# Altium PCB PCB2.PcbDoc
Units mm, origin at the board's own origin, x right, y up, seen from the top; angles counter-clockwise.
Board outline 80 x 60 mm, 2 copper layers (Top Layer, Bottom Layer); 29 components, 19 nets, 66 pads, 0 vias.
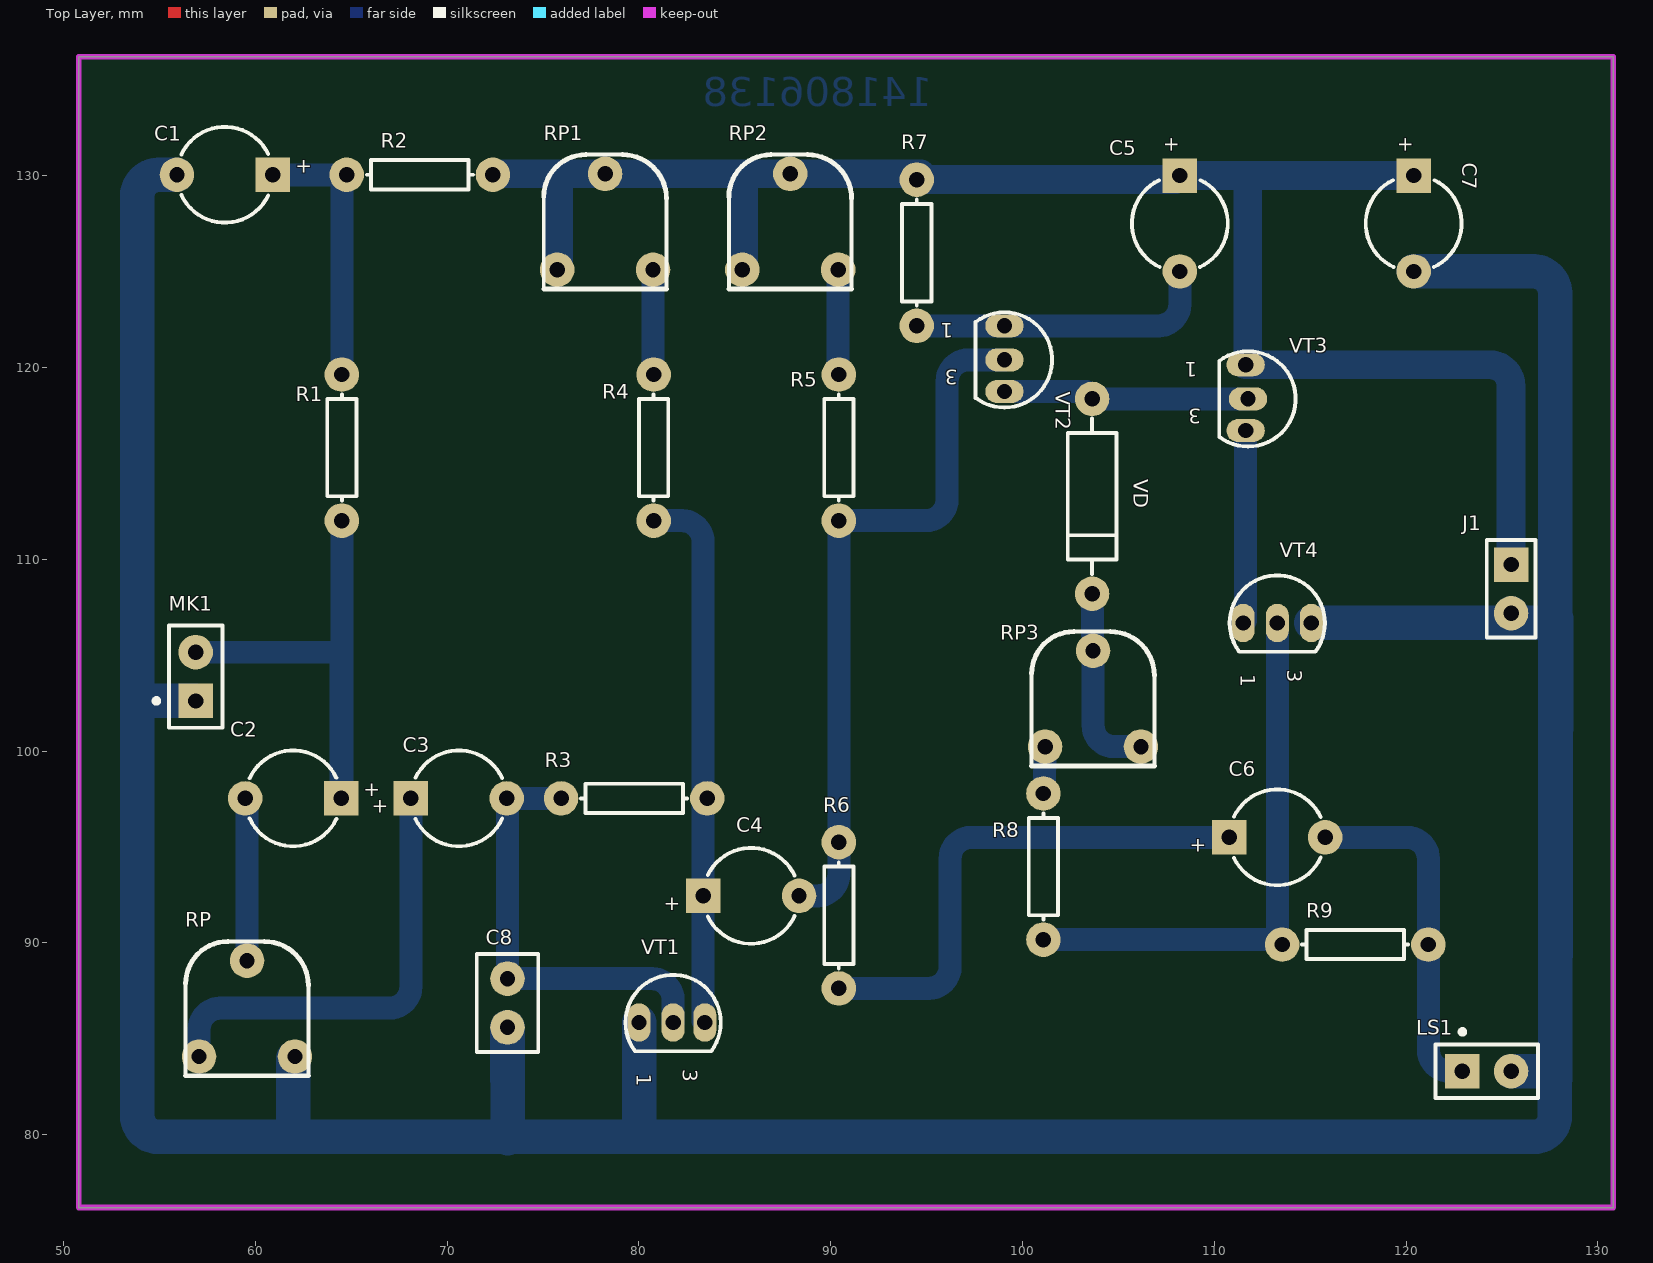
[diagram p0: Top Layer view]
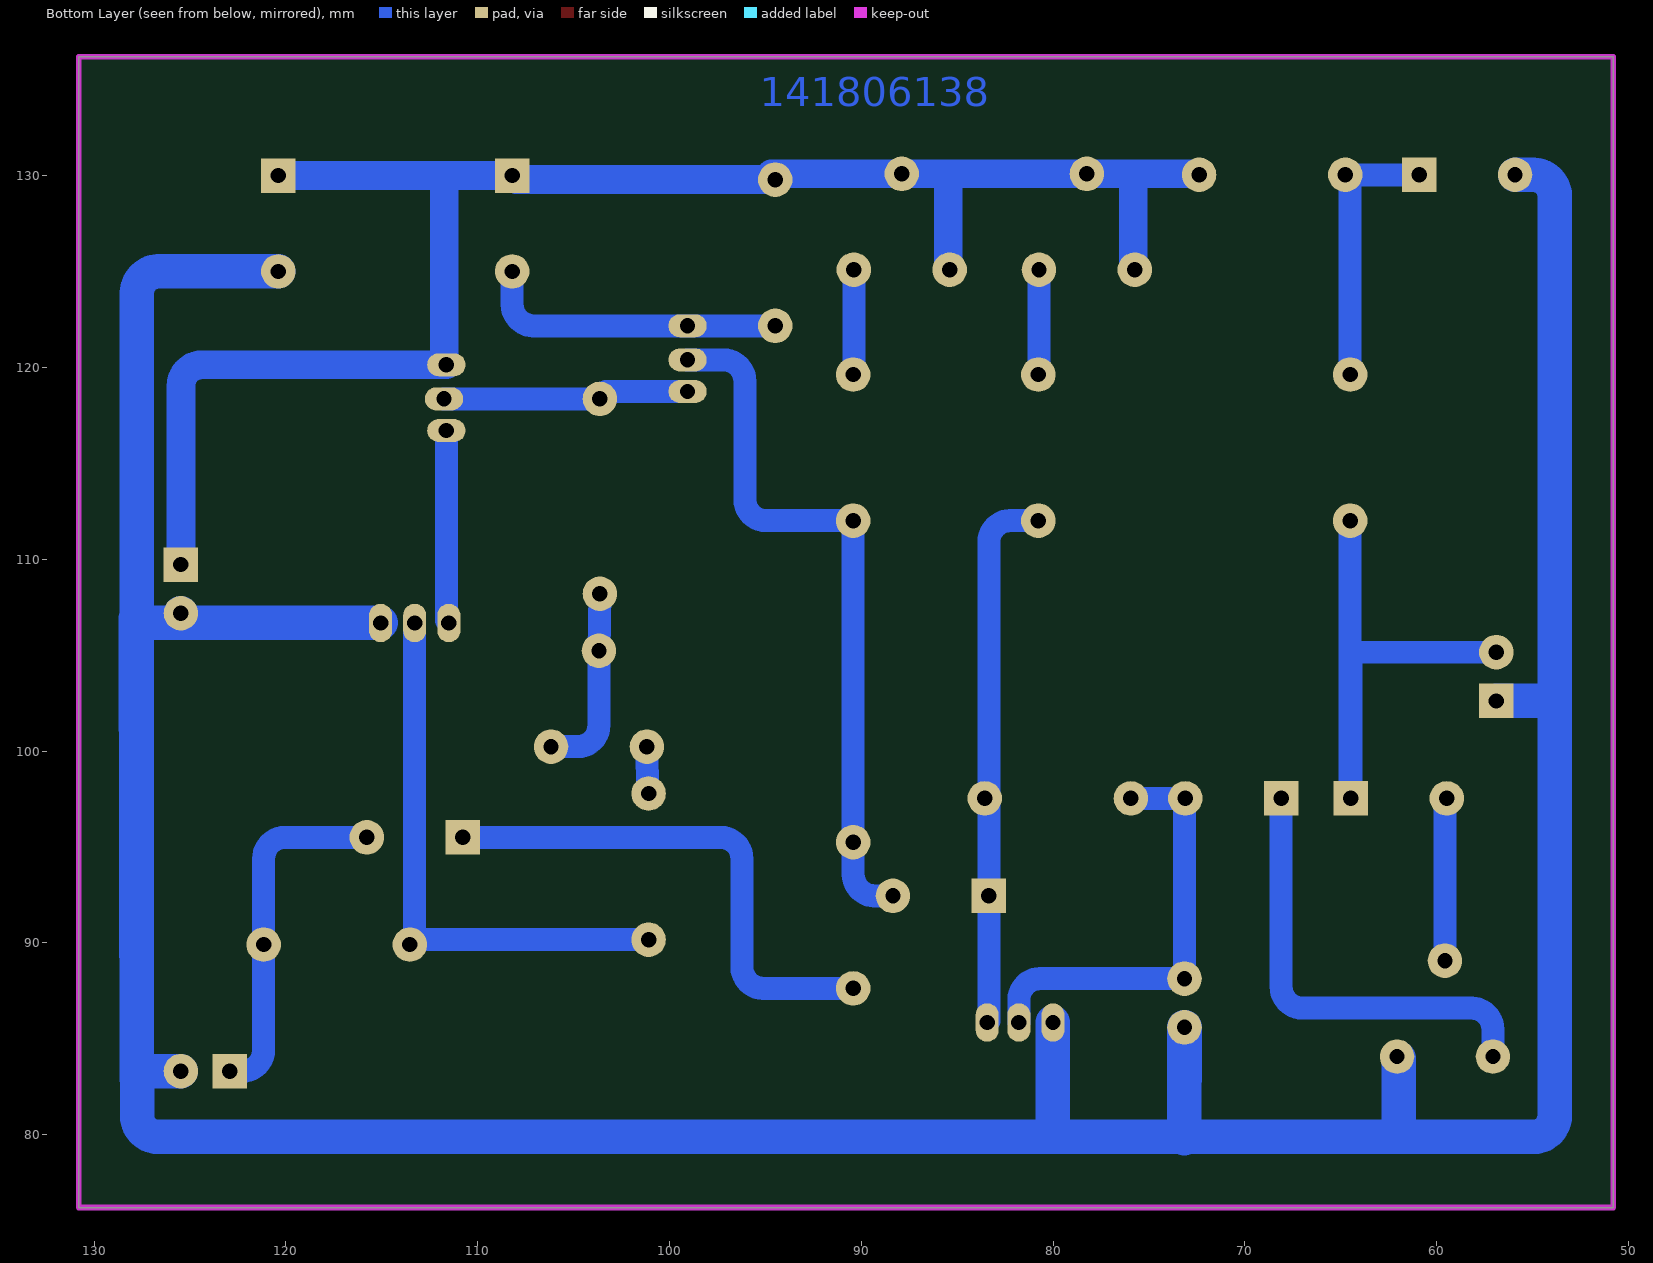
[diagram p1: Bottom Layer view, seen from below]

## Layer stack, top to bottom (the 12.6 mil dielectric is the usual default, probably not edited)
Top Layer: signal copper 0.0356
Dielectric: dielectric 0.32, FR-4, Dk 4.8
Bottom Layer: signal copper 0.0356

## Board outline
50.8,76.2 130.8,76.2 130.8,136.2 50.8,136.2

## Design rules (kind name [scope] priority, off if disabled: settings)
Clearance [All] p1: gap=0.203
ComponentClearance [All] p1: gap=0.254 collisioncheckmode=0
PolygonConnect [All] p1: connectstyle=Relief reliefconductorwidth=0.254 reliefentries=4 polygonreliefangle="90 Angle"
RoutingLayers [All] p1: top layer_v5=FALSE bottom layer_v5=TRUE
RoutingVias [All] p1: holewidth=0.8 width=2 viastyle="Through Hole" minholewidth=0.8 minwidth=1.8 maxholewidth=0.8 maxwidth=2
SolderMaskExpansion [All] p1: expansion=0.102
TestPointUsage [All] p1: valid=0 allowmultiple=FALSE
Testpoint [All] p1: side=15 testpointundercomponent=TRUE minsize=1.016 maxsize=2.54 preferedsize=1.524 minholesize=0 maxholesize=1.016 preferedholesize=0.813 testpointgrid=0.025 style=1023 order=-539222988
Width Width_GND [InNet('GND')] p1: maxlimit=1.8 minlimit=1 preferedwidth=1.8 minimp=50.000000 maximp=50.000000 favimp=50.000000
Width Width_VCC [InNet('VCC')] p2: maxlimit=1.5 minlimit=1.5 preferedwidth=1.5
Width [All] p3: maxlimit=1.2 minlimit=1.2 preferedwidth=1.2
16 further rules are at their usual default settings.

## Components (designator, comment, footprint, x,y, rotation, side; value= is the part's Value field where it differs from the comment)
C1 "Cap Pol1" CAPPR5-5x5 58.42,130.048 r180 top
C2 "Cap Pol1" CAPPR5-5x5 61.976,97.536 r180 top
C3 "Cap Pol1" CAPPR5-5x5 70.612,97.536 r0 top
C4 "Cap Pol1" CAPPR5-5x5 85.852,92.456 r0 top
C5 "Cap Pol1" CAPPR5-5x5 108.204,127.508 r270 top
C6 "Cap Pol1" CAPPR5-5x5 113.284,95.504 r0 top
C7 "Cap Pol1" CAPPR5-5x5 120.396,127.508 r270 top
C8 "Cap" CAPR2.54-5.1x3.2 73.152,86.868 r90 top
J1 "MHDR1X2" HDR1X2 125.476,109.728 r270 top
LS1 "Speaker" PIN2 122.936,83.312 r0 top
MK1 "Mic" PIN2 56.896,102.616 r90 top
R1 "Res2" AXIAL-0.3 64.516,115.824 r90 top
R2 "Res2" AXIAL-0.3 68.58,130.048 r0 top
R3 "Res2" AXIAL-0.3 79.756,97.536 r0 top
R4 "Res2" AXIAL-0.3 80.772,115.824 r90 top
R5 "Res2" AXIAL-0.3 90.424,115.824 r90 top
R6 "Res2" AXIAL-0.3 90.424,91.44 r90 top
R7 "Res2" AXIAL-0.3 94.488,125.984 r90 top
R8 "Res2" AXIAL-0.3 101.092,93.98 r270 top
R9 "Res2" AXIAL-0.3 117.348,89.916 r0 top
RP "RPot" RM065 639.572,989.076 r0 top
RP1 "RPot" RM065 658.241,1030.097 r0 top
RP2 "RPot" RM065 667.893,1030.097 r0 top
RP3 "RPot" RM065 683.679,1005.231 r0 top
VD "4148" DIODE-0.4 103.632,113.284 r270 top
VT1 "9014" BCY-W3/E4#1 81.788,85.852 r270 top
VT2 "9015" BCY-W3/E4#1 99.06,120.396 r180 top
VT3 "8050" BCY-W3/E4#2 111.76,118.364 r180 top
VT4 "8550" BCY-W3/E4#3 113.284,106.68 r270 top

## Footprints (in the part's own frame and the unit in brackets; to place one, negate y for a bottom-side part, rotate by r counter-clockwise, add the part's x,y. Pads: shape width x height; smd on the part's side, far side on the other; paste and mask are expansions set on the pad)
AXIAL-0.3 [mm] "Resistor; 2 Leads"
  round 1.8 hole 0.8: 1(-3.81,0) 2(3.81,0)
  silkscreen extent -2.77,-0.76 2.77,0.76
BCY-W3/E4#1 [mm] "TO, Flat Index; 3 In-Line, Axial Leads; Body Dia. 4.7mm"
  oval 2x1.2 hole 0.8: 1(0,-1.778) 2(0,0) 3(0,1.651)
  silkscreen extent -2.48,-2.48 1.5,2.48
BCY-W3/E4#2 [mm] "TO, Flat Index; 3 In-Line, Axial Leads; Body Dia. 4.7mm"
  oval 2x1.2 hole 0.8: 1(0.127,-1.778) 2(0,0) 3(0.127,1.651)
  silkscreen extent -2.48,-2.48 1.5,2.48
BCY-W3/E4#3 [mm] "TO, Flat Index; 3 In-Line, Axial Leads; Body Dia. 4.7mm"
  oval 2x1.2 hole 0.8: 1(0,-1.778) 2(0,0) 3(0,1.778)
  silkscreen extent -2.48,-2.48 1.5,2.48
CAPPR5-5x5 [mm] "Capacitor, Electrolytic, Radial; Body 5 x 5 mm (Dia.xH typ); Pin Spacing 5 mm (typ)"
  rect 1.8x1.8 hole 0.8: 1(-2.5,0)
  round 1.8 hole 0.8: 2(2.5,0)
  silkscreen extent -2.26,-2.5 2.27,2.5
CAPR2.54-5.1x3.2 [mm] "Capacitor, Ceramic, Thru-Hole, Dipped Radial; Body 5.1 x 3.2 mm (WxT) Pin Spacing 2.54 mm (typ)"
  round 1.8 hole 0.8: 1(-1.27,0) 2(1.27,0)
  silkscreen extent -2.55,-1.6 2.55,1.6
DIODE-0.4 [mm] "Tunnel Diode - Dependent Source Model; 2 Leads"
  round 1.8 hole 0.8: 1(-5.08,0) 2(5.08,0)
  silkscreen extent -4.06,-1.27 4.06,1.27
HDR1X2 [mm] "Connector; Header; 2 Position"
  rect 1.8x1.8 hole 0.8: 1(0,0)
  round 1.8 hole 0.8: 2(2.54,0)
  silkscreen extent -1.27,-1.27 3.81,1.27
PIN2 [mm] "Photosensitive Diode; 2 Leads"
  rect 1.8x1.8 hole 0.8: 1(0,0)
  round 1.8 hole 0.8: 2(2.54,0)
  silkscreen extent -1.4,-1.4 3.94,2.17
RM065 [mm]
  round 1.8 hole 0.8: 1(-582.5,-905) 2(-580,-900) 3(-577.5,-905)
  silkscreen extent -583.2,-906 -576.8,-899

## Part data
C1 C2 C3 C4 C5 C6 C7: "Polarized Capacitor (Radial)"
C8: "Capacitor"
J1: library part "Header 2", "Header, 2-Pin"
LS1: "Loudspeaker"
MK1: library part Mic2, "Microphone"
R1 R2 R3 R4 R5 R6 R7 R8 R9: "Resistor"
RP RP1 RP2 RP3: "Potentiometer"
VD: library part "Diode 1N4148", "High Conductance Fast Diode"
VT1: library part 2N3904, "NPN General Purpose Amplifier"
VT2 VT3 VT4: library part 2N3906, "PNP General Purpose Amplifier"

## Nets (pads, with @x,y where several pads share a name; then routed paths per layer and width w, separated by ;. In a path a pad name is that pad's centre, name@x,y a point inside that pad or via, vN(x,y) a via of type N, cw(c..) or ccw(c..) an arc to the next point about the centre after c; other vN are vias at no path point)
GND: C1.2 C7.2 C8.1 J1.2 LS1.2 MK1.1 RP.3 VT1.1 VT4.3 | length 234.4
  Bottom Layer w1.8: 53.975,102.616 MK1.1 ; C1.2 54.966,130.048 ccw(c54.966,128.93) 53.848,128.93 53.848,81.001 ccw(c54.966,81.001) 54.966,79.883 126.644,79.883 ccw(c126.644,81.001) 127.762,81.001 127.762,82.169 127.765,83.312 ; 61.976,79.883 RP.3@61.976,83.98 ; C8.1 73.167,79.808 ; 80.01,79.883 VT1.1 ; VT4.3 127.578,106.68 ; C7.2 126.648,125.008 cw(c126.648,123.89) 127.765,123.89 127.765,83.312 ; LS1.2 127.765,83.312 ; J1.2@125.476,106.68 J1.2 ; 127.832,106.932 127.765,83.312
NetC1_1: C1.1 R1.2 R2.1 | length 14
  Bottom Layer w1.2: C1.1 R2.1 ; R1.2 R2.1@64.516,129.794
NetC2_1: C2.1 MK1.2 R1.1 | length 29.1
  Bottom Layer w1.2: MK1.2 64.516,105.15 ; 64.476,104.521 C2.1 ccw(c64.476,97.576) 64.516,97.576 R1.1
NetC2_2: C2.2 RP.2 | length 8.5
  Bottom Layer w1.2: C2.2 cw(c59.476,97.44) 59.572,97.44 RP.2
NetC3_1: C3.1 RP.1 | length 23.5
  Bottom Layer w1.2: RP.1 57.072,85.482 cw(c58.19,85.482) 58.19,86.6 66.994,86.6 ccw(c66.994,87.718) 68.112,87.718 C3.1
NetC3_2: C3.2 C8.2 R3.1 VT1.2 | length 22.7
  Bottom Layer w1.2: R3.1 C3.2 cw(c73.112,97.496) 73.152,97.496 C8.2 80.67,88.138 cw(c80.67,87.02) 81.788,87.02 VT1.2
NetC4_1: C4.1 R3.2 R4.1 VT1.3 | length 28.2
  Bottom Layer w1.2: R4.1 82.234,112.014 cw(c82.234,110.896) 83.352,110.896 VT1.3@83.352,85.939
NetC4_2: C4.2 R5.1 R6.2 VT2.2 | length 37.2
  Bottom Layer w1.2: C4.2 89.306,92.456 ccw(c89.306,93.574) 90.424,93.574 R5.1 94.957,112.014 ccw(c94.957,113.132) 96.075,113.132 96.075,119.278 cw(c97.193,119.278) 97.193,120.396 VT2.2
NetC5_2: C5.2 R7.1 VT2.1 | length 16.1
  Bottom Layer w1.2: R7.1 107.086,122.174 ccw(c107.086,123.292) 108.204,123.292 C5.2
NetC6_1: C6.1 R6.1 | length 27.3
  Bottom Layer w1.2: R6.1 95.107,87.63 ccw(c95.107,88.748) 96.225,88.748 96.225,94.386 cw(c97.343,94.386) 97.343,95.504 C6.1
NetC6_2: C6.2 LS1.1 R9.2 | length 17.7
  Bottom Layer w1.2: C6.2 120.04,95.504 cw(c120.04,94.386) 121.158,94.386 121.158,84.43 ccw(c122.276,84.43) LS1.1@122.276,83.312
NetR4_2: R4.2 RP1.3 | length 5.4
  Bottom Layer w1.2: R4.2@80.741,119.665 RP1.3
NetR5_2: R5.2 RP2.3 | length 5.4
  Bottom Layer w1.2: R5.2@90.393,119.665 RP2.3
NetR8_1: R8.1 RP3.1 | length 2.5
  Bottom Layer w1.2: R8.1 ccw(c101.092,97.839) 101.141,97.839 RP3.1
NetR8_2: R8.2 R9.1 VT4.2 | length 28.7
  Bottom Layer w1.2: R8.2 113.284,90.17 VT4.2
NetRP3_2: RP3.2 RP3.3 VD.2 | length 10
  Bottom Layer w1.2: VD.2 RP3.2 103.679,101.349 ccw(c104.797,101.349) 104.797,100.231 RP3.3
NetVD_1: VD.1 VT2.3 VT3.2 | length 12.9
  Bottom Layer w1.2: VT2.3 103.251,118.745 cw(c103.251,118.364) VD.1 VT3.2
NetVT3_3: VT3.3 VT4.1 | length 9.9
  Bottom Layer w1.2: VT4.1@111.633,106.807 VT3.3
VCC: C5.1 C7.1 J1.1 R2.2 R7.2 RP1.1 RP1.2 RP2.1 RP2.2 VT3.1 | length 91.5
  Bottom Layer w1.5: R2.2 cw(c72.439,130.048) 72.439,130.097 R7.2@94.693,130.097 ; RP1.1@75.819,125.175 75.819,130.097 ; RP2.1 ccw(c85.393,125.175) 85.471,125.175 85.471,130.097 ; R7.2 C5.1@107.99,129.794 ; C5.1 C7.1 ; VT3.1 124.358,120.142 cw(c124.358,119.024) 125.476,119.024 J1.1 ; VT3.1@111.75,120.259 111.75,130.008

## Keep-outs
Keep-Out Layer:
  the board outline again, w0.3

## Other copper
Bottom Layer:
  text "141806138" at 95.3,133.625 h1.52

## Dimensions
50.8,76.2 to 130.8,76.2 on Mechanical 1
50.8,76.2 to 50.8,136.2 on Mechanical 1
